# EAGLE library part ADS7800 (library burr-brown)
12-Bit 3us Sampling ADC
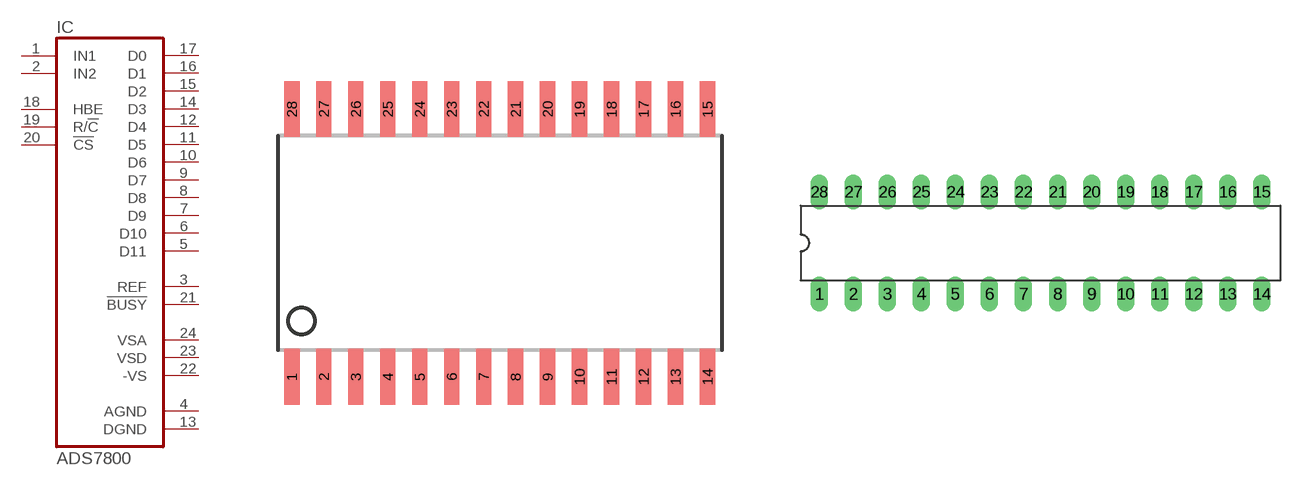
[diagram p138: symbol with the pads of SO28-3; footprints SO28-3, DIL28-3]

Designator prefix IC

## ADS7800U (OC_FARNELL: unknown; OC_NEWARK: unknown)  [SO28-3]
1  IN1  in
2  IN2  in
3  REF  out
4  AGND  pwr
5  D11  out
6  D10  out
7  D9  out
8  D8  out
9  D7  out
10  D6  out
11  D5  out
12  D4  out
13  DGND  pwr
14  D3  out
15  D2  out
16  D1  out
17  D0  out
18  HBE  in
19  R/!C  in
20  !CS  in
21  !BUSY  out
22  -VS  pwr
23  VSD  pwr
24  VSA  pwr

## ADS7800P (OC_FARNELL: unknown; OC_NEWARK: unknown)  [DIL28-3]
Pads as for SO28-3

## Footprint SO28-3 (pad centres in mm)
Small Outline Package
smd 0.61 x 2.21: 1 -8.255,-5.315; 2 -6.985,-5.315; 3 -5.715,-5.315; 4 -4.445,-5.315; 5 -3.175,-5.315; 6 -1.905,-5.315; 7 -0.635,-5.315; 8 0.635,-5.315; 9 1.905,-5.315; 10 3.175,-5.315; 11 4.445,-5.315; 12 5.715,-5.315; 13 6.985,-5.315; 14 8.255,-5.315; 15 8.255,5.315; 16 6.985,5.315; 17 5.715,5.315; 18 4.445,5.315; 19 3.175,5.315; 20 1.905,5.315; 21 0.635,5.315; 22 -0.635,5.315; 23 -1.905,5.315; 24 -3.175,5.315; 25 -4.445,5.315; 26 -5.715,5.315; 27 -6.985,5.315; 28 -8.255,5.315

## Footprint DIL28-3 (pad centres in mm)
Dual In Line 0.3 inch
drill 0.813 long: 1 -16.51,-3.81; 2 -13.97,-3.81; 3 -11.43,-3.81; 4 -8.89,-3.81; 5 -6.35,-3.81; 6 -3.81,-3.81; 7 -1.27,-3.81; 8 1.27,-3.81; 9 3.81,-3.81; 10 6.35,-3.81; 11 8.89,-3.81; 12 11.43,-3.81; 13 13.97,-3.81; 14 16.51,-3.81; 15 16.51,3.81; 16 13.97,3.81; 17 11.43,3.81; 18 8.89,3.81; 19 6.35,3.81; 20 3.81,3.81; 21 1.27,3.81; 22 -1.27,3.81; 23 -3.81,3.81; 24 -6.35,3.81; 25 -8.89,3.81; 26 -11.43,3.81; 27 -13.97,3.81; 28 -16.51,3.81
